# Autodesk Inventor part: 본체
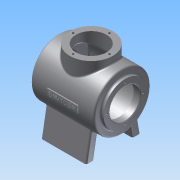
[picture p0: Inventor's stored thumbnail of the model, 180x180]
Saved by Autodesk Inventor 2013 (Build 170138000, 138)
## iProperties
Created: 2015-01
Part Number: 본체
Document SubType Name: Modeling
Designer: kb54305
Density: 1 g/cm^3
Material: 일반
Author: kb54305
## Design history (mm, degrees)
sketch "스케치1"
  geometry: L1 (-61, 0)-(61, 0); L2 (-61, 27)-(-49, 27); L3 (-49, 27)-(-49, 45); L4 (-49, 45)-(48, 45); L5 (48, 45)-(48, 27); L6 (48, 27)-(61, 27); L7 (61, 27)-(61, 38); L8 (61, 38)-(56, 38); L9 (56, 38)-(56, 50); L10 (56, 50)-(-56, 50); L11 (-56, 50)-(-56, 38); L12 (-56, 38)-(-61, 38); L13 (-61, 38)-(-61, 27); 2 further points
  constraints: 26 end point, 10 parallel, 2 vertical alignment, 1 coincident, 1 collinear, 1 horizontal, 1 midpoint, 1 perpendicular
  dimensions: "d0" = 122 distance of L1.start L1.end; "d1" = 54 diameter of L2 L1; "d2" = 90 diameter of L4 L1; "d3" = 54 diameter of L6 L1; "d4" = 76 diameter of L12.end L1; "d5" = 100 diameter of L10 L1; "d6" = 76 diameter of L8 L1; "d7" = 5 distance between parallel lines of L11 L13; "d8" = 7 distance between parallel lines of L3 L11; "d9" = 5 distance between parallel lines of L7 L9; "d10" = 8 distance between parallel lines of L9 L5
revolve "회전1" sketch "스케치1" stored, may be unused: angle "d11" = 90 deg
sketch "스케치2"
  geometry: L1 (-39.336, -30.865)-(-48, -80); L2 (-48, -80)-(-34, -80); L3 (-34, -80)-(-27.282, -41.901); L4 (27.282, -41.901)-(34, -80); L5 (34, -80)-(48, -80); L6 (48, -80)-(39.336, -30.865); A1 r 50 centre (0, 0) between (-39.336, -30.865) and (-27.282, -41.901) reference; 1 further point
  constraints: 12 end point, 4 point on circle, 3 equal length, 1 collinear, 1 horizontal, 1 parallel
  dimensions: "d12" = 14 distance of L1.end L2.end; "d13" = 80 deg angle of L2 L3; "d14" = 96 distance of L5.end L1.end; "d15" = 80 deg angle of L5 L4; "d16" = 100 deg angle of L5 L6; "d17" = 80 distance from line of L2 point (0, 0)
extrude "돌출1" join sketch "스케치2" stored distance "d18" = 80; taper "d19" = 0 deg
node "작업 평면1"
sketch "스케치3"
  geometry: L1 (-101, 86)-(-101, 10) reference; C1 r 38 at (-39, 48); 2 further points
  constraints: 1 centre point, 1 coincident, 1 horizontal alignment, 1 midpoint
  dimensions: "d21" = 76 diameter of C1; "d55" = 62 distance from line of point (-39, 48) L1
extrude "돌출2" join sketch "스케치3" stored distance "d22" = 80; taper "d23" = 0 deg
sketch "스케치4"
  geometry: C1 r 38 at (0, 0) reference; C2 r 27 at (0, 0)
  constraints: 1 centre point, 1 coincident
  dimensions: "d24" = 54 diameter of C2
extrude "돌출3" cut sketch "스케치4" stored distance "d25" = 80; taper "d26" = 0 deg
sketch "스케치7" dims "d27" = 64
  geometry: C1 r 27 at (0, 0) reference; C2 r 38 at (0, 0) reference; 2 further points
  constraints: 2 horizontal alignment, 1 coincident, 2 other
hole "구멍1" sketch "스케치7" at (32, 0) diameter "d28" = 3.242; stored, may be unused: countersink angle "d32" = 90 deg, drill point angle "d34" = 118 deg; dims "d29" = 8, "d30" = 4, "d31" = 2, "d33" = 10
node "작업 평면2"
sketch "스케치8" dims "d38" = 64
  geometry: C1 r 27 at (0, 0) reference; C2 r 38 at (0, 0) reference; 2 further points
  constraints: 2 vertical alignment, 1 coincident, 2 other
hole "구멍2" sketch "스케치8" at (0, 32) diameter "d39" = 3.242; stored, may be unused: countersink angle "d43" = 90 deg, drill point angle "d45" = 118 deg; dims "d40" = 8, "d41" = 4, "d42" = 2, "d44" = 10
fillet "모깎기1" dims "d49" = 3
fillet "모깎기2" dims "d50" = 3
fillet "모깎기3" dims "d51" = 3
chamfer "모따기1" distance "d52" = 1; stored, may be unused: second distance "d53" = 2, angle "d54" = 45 deg
node "작업 평면3"
sketch "스케치12"
  geometry: L1 (-26, 6)-(28, 6); L2 (28, 6)-(28, -6); L3 (28, -6)-(-26, -6); L4 (-26, -6)-(-26, 6); L5 (-37, 62)-(39, 62) reference; L6 (-61, 38)-(-61, -38) reference; 5 further points
  constraints: 8 end point, 4 midpoint, 2 parallel, 1 horizontal, 1 horizontal alignment, 1 perpendicular, 1 vertical alignment
  dimensions: "d61" = 54 distance of L1.start L1.end; "d62" = 12 distance of L3.end L1.start
feature "엠보싱1" sketch "스케치12" dims "d63" = 2, "d64" = 0
sketch "스케치13"
  geometry: L1 (28, 6)-(-26, 6) reference; L2 (-26, -6)-(-26, 6) reference; 4 further points
  constraints: 2 midpoint, 1 coincident, 1 horizontal alignment, 1 vertical alignment, 1 other
feature "엠보싱2" sketch "스케치13" dims "d65" = 0.5, "d66" = 0
node "솔리드1"
pattern_circular "원형 패턴1" dims angle "d36" = 360 deg
mirror "대칭1"
pattern_circular "원형 패턴2" dims angle "d47" = 360 deg
other parameters: "d20" = -142, "d56" = -157.5
